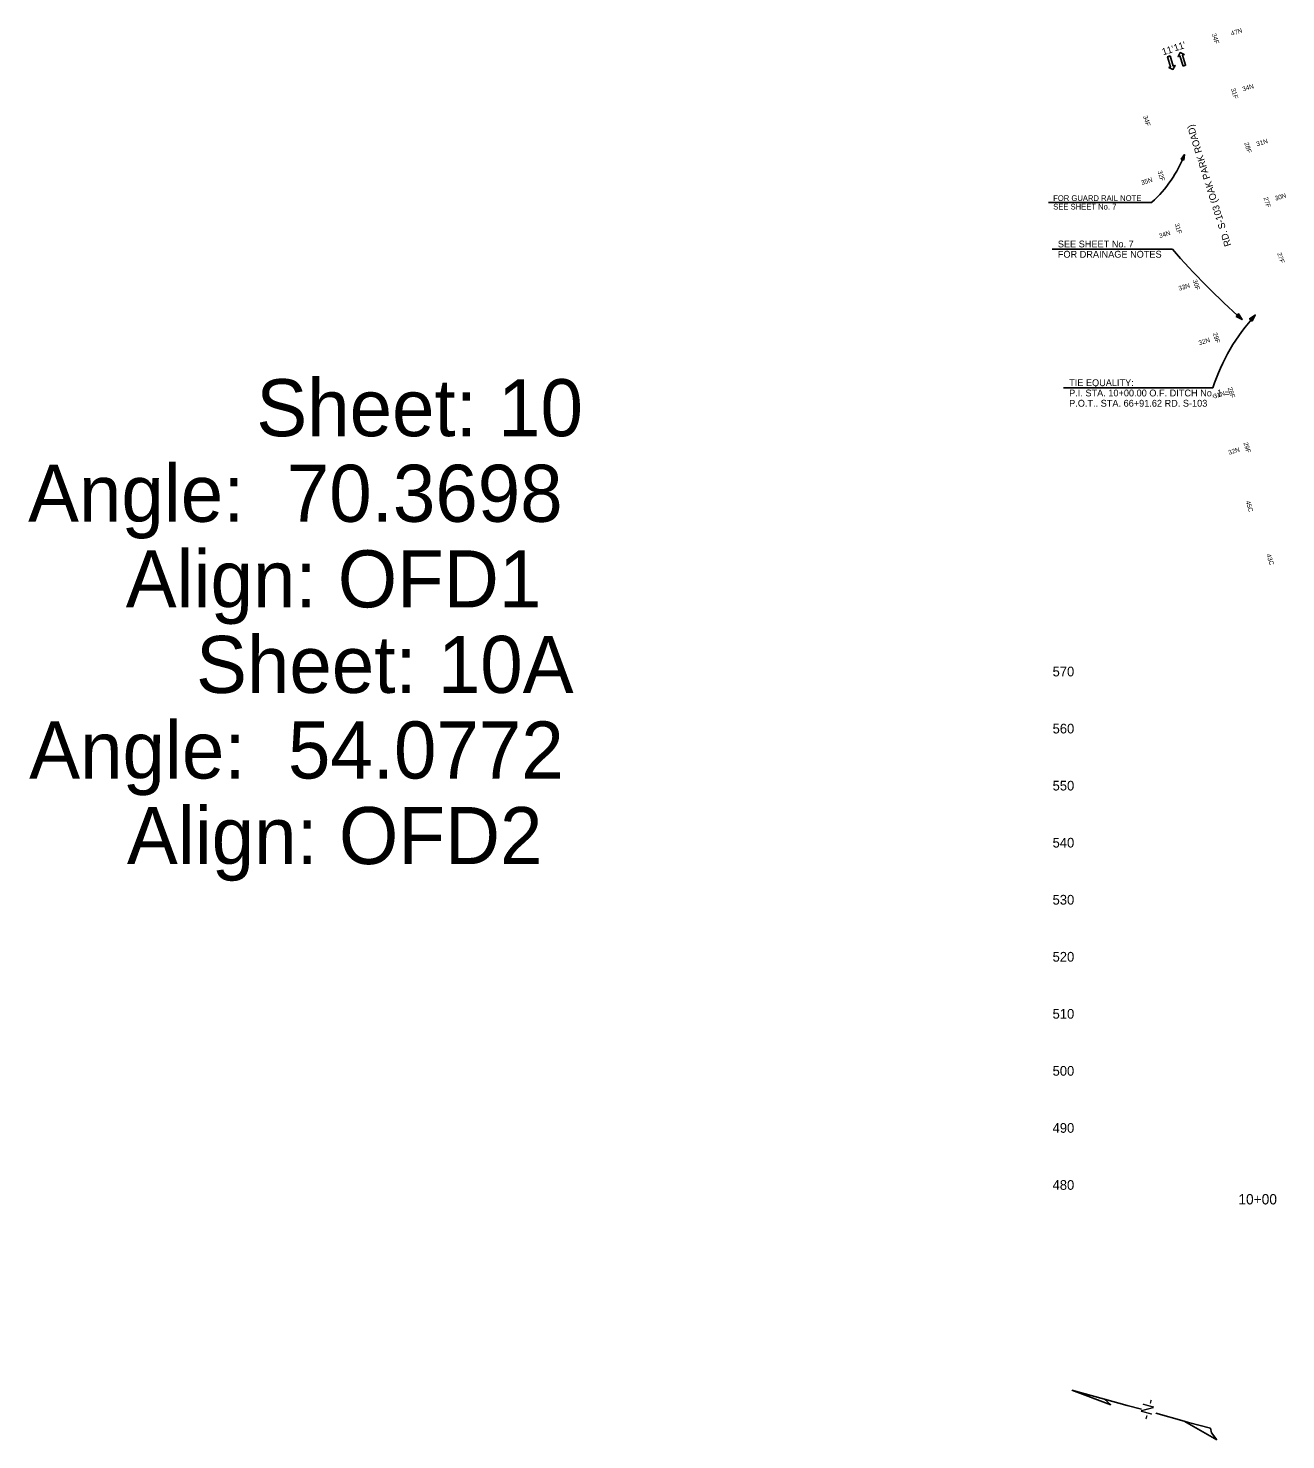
# Model space of a CAD drawing. Extents: x 1964850 to 1967424, y 1116563 to 1122204.
# Drawn here: x 1964868 to 1965970, y 1120957 to 1122194 of the extents above; entities that cross this region are included whole.
import ezdxf

# ---------------------------------------------------------------- set-up
doc = ezdxf.new("R2010")
doc.units = 0
for name, color, linetype in [('RD_DDB_Profile_Elev', 7, 'Continuous'), ('RD_DDB_StaTX', 7, 'Continuous'), ('RD_EX_Misc', 7, 'Continuous'), ('RD_HC_Data', 7, 'Continuous'), ('RD_PD_Final_LnLine', 7, 'Continuous'), ('RD_PD_Final_TX', 7, 'Continuous'), ('RD_PD_TX_CstnLmt', 7, 'Continuous'), ('RD_TX_Drainage', 7, 'Continuous'), ('RD_TX_Misc1', 7, 'Continuous'), ('RD_TX_RoadID', 7, 'Continuous')]:
    doc.layers.add(name, color=color, linetype=linetype)

msp = doc.modelspace()

# ---------------------------------------------------------------- linework, layer by layer
at = {"layer": 'RD_EX_Misc'}
for p, q in [((1965816.9, 1120987.1), (1965782.7, 1121000)), ((1965782.7, 1121000), (1965811.3, 1120992.1)), ((1965811.3, 1120992.1), (1965831.1, 1120986.7)), ((1965811.3, 1120992.1), (1965816.9, 1120987.1)), ((1965831.1, 1120986.7), (1965843.7, 1120983.2)), ((1965856.4, 1120979.7), (1965881.3, 1120972.9)), ((1965881.3, 1120972.9), (1965885.1, 1120971.8)), ((1965909.7, 1120956.5), (1965881.3, 1120972.9)), ((1965885.1, 1120971.8), (1965904.2, 1120966.6))]:
    msp.add_line(p, q, dxfattribs=at)
msp.add_lwpolyline([(1965904.2, 1120966.6), (1965905.2, 1120962.7), (1965909.7, 1120956.5)], dxfattribs=at)
at = {"layer": 'RD_HC_Data'}
msp.add_line((1965906.3, 1121878.5), (1965775.4, 1121878.5), dxfattribs=at)
msp.add_lwpolyline([(1965940.8, 1121937), (1965943.5, 1121942.3), (1965938.5, 1121939.1)], close=True, dxfattribs=at)
msp.add_arc((1966073.9, 1121823.6), 176.3, 137.6645, 161.8625, dxfattribs=at)
at = {"layer": 'RD_PD_Final_LnLine'}
for points in [[(1965868.9, 1122169.4), (1965866.6, 1122168.7), (1965869.3, 1122159.9), (1965867.8, 1122159.4), (1965871.3, 1122157.6), (1965873.2, 1122161.1), (1965871.6, 1122160.6)], [(1965880.2, 1122160.6), (1965882.5, 1122161.3), (1965879.7, 1122170.1), (1965881.3, 1122170.6), (1965877.8, 1122172.4), (1965875.9, 1122168.9), (1965877.5, 1122169.4)]]:
    msp.add_lwpolyline(points, close=True, dxfattribs=at)
at = {"layer": 'RD_TX_Drainage'}
msp.add_line((1965871, 1122000.1), (1965765.5, 1122000.1), dxfattribs=at)
msp.add_lwpolyline([(1965926.7, 1121941.1), (1965932, 1121938.4), (1965928.7, 1121943.4)], close=True, dxfattribs=at)
msp.add_arc((1966346.5, 1122410.1), 627.9, 220.769, 228.6953, dxfattribs=at)
at = {"layer": 'RD_TX_Misc1'}
msp.add_line((1965853, 1122041.1), (1965762.2, 1122041.1), dxfattribs=at)
msp.add_lwpolyline([(1965881, 1122078.1), (1965881.5, 1122083), (1965878.6, 1122079)], close=True, dxfattribs=at)
msp.add_arc((1965779.7, 1122121.7), 108.9, 312.2863, 339.2152, dxfattribs=at)

# ---------------------------------------------------------------- texts
at = {"layer": 'RD_DDB_Profile_Elev'}
for s, p in [('570', (1965765.9, 1121625.6)), ('560', (1965765.9, 1121575.6)), ('550', (1965765.9, 1121525.6)), ('540', (1965765.9, 1121475.6)), ('530', (1965765.9, 1121425.6)), ('520', (1965765.9, 1121375.6)), ('510', (1965765.9, 1121325.6)), ('500', (1965765.9, 1121275.6)), ('490', (1965765.9, 1121225.6)), ('480', (1965765.9, 1121175.6))]:
    msp.add_text(s, height=8.5, dxfattribs=at).set_placement(p)
at = {"layer": 'RD_DDB_StaTX'}
msp.add_text('10+00', height=9, dxfattribs=at).set_placement((1965928.7, 1121162.8))
at = {"layer": 'RD_EX_Misc'}
msp.add_text('-N-', height=10, rotation=74.6355, dxfattribs=at).set_placement((1965851.3, 1120973.1))
at = {"layer": 'RD_HC_Data'}
for s, p in [('TIE EQUALITY:', (1965780.4, 1121880)), ('P.I. STA. 10+00.00 O.F. DITCH No, 1 =', (1965780.4, 1121871)), ('P.O.T.. STA. 66+91.62 RD. S-103', (1965780.4, 1121862))]:
    msp.add_text(s, height=6, dxfattribs=at).set_placement(p)
at = {"layer": 'RD_PD_Final_TX'}
for p in [(1965873.1, 1122173.4), (1965862.8, 1122169.9)]:
    msp.add_text("11'", height=6, rotation=17.3569, dxfattribs=at).set_placement(p)
at = {"layer": 'RD_PD_TX_CstnLmt'}
for s, p in [('34F', (1965905.4, 1122188.6)), ('31F', (1965922.1, 1122140.6)), ('34F', (1965845.2, 1122116.5)), ('28F', (1965933.8, 1122093)), ('32F', (1965857.8, 1122068.3)), ('27F', (1965950.6, 1122045.2)), ('31F', (1965872.7, 1122022.2)), ('27F', (1965962.7, 1121996.4)), ('30F', (1965888.5, 1121972.8)), ('29F', (1965906.2, 1121926.3)), ('28F', (1965919.3, 1121878.3)), ('29F', (1965933.1, 1121830.2)), ('45C', (1965935, 1121778.9)), ('43C', (1965953.2, 1121732.3))]:
    msp.add_text(s, height=4, rotation=287.3569, dxfattribs=at).set_placement(p)
at = {"layer": 'RD_TX_Drainage'}
for s, p in [('47N', (1965922.8, 1122187.1)), ('34N', (1965932.9, 1122138.3)), ('31N', (1965945.2, 1122090.2)), ('35N', (1965844.2, 1122056.3)), ('30N', (1965961.3, 1122042.5)), ('34N', (1965859.8, 1122009.7)), ('33N', (1965876.9, 1121963.6)), ('32N', (1965894.6, 1121915.8)), ('31N', (1965907.6, 1121869.1)), ('32N', (1965920.6, 1121819.8))]:
    msp.add_text(s, height=4, rotation=17.3569, dxfattribs=at).set_placement(p)
for s, p in [('SEE SHEET No. 7', (1965770.5, 1122001.6)), ('FOR DRAINAGE NOTES', (1965770.5, 1121992.6))]:
    msp.add_text(s, height=6, dxfattribs=at).set_placement(p)
at = {"layer": 'RD_TX_Misc1'}
for s, height, p in [('FOR GUARD RAIL NOTE', 5, (1965766.4, 1122042.3)), ('SEE SHEET No. 7', 5, (1965766.4, 1122034.8)), ('Sheet: 10', 50, (1965068.1, 1121836.1)), ('Angle:  70.3698', 50, (1964868.1, 1121761.1)), ('Align: OFD1', 50, (1964953.7, 1121686.1)), ('Sheet: 10A', 50, (1965015.3, 1121611.1)), ('Angle:  54.0772', 50, (1964869.1, 1121536.1)), ('Align: OFD2', 50, (1964954.7, 1121461.1))]:
    msp.add_text(s, height=height, dxfattribs=at).set_placement(p)
at = {"layer": 'RD_TX_RoadID'}
msp.add_text('RD. S-103 (OAK PARK ROAD)', height=6, rotation=107.3569, dxfattribs=at).set_placement((1965922.5, 1122003.5))

doc.saveas('drawing.dxf')
